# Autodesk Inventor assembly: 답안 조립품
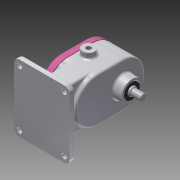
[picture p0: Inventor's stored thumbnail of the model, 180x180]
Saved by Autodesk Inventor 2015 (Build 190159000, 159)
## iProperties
Created: 2020-09
Part Number: 답안 조립품
Document SubType Name: Assembly
Designer: 1015698
Author: 1015698
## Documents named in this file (11)
- C:\Users\1015698\Desktop\700906V1049\답안 조립품.iam
- C:\Users\1015698\Desktop\700906V1049\20200919 부품.ipt
- C:\Users\1015698\Desktop\700906V1049\메인축.ipt
- C:\Users\1015698\Desktop\700906V1049\키 6 x 6 x 18.ipt
- C:\Users\1015698\Desktop\700906V1049\스퍼기어.ipt
- C:\Users\1015698\Desktop\700906V1049\베어링부시.ipt
- C:\Users\1015698\Desktop\700906V1049\서브축.ipt
- C:\Users\1015698\Desktop\700906V1049\개스킷.ipt
- C:\Users\1015698\Desktop\700906V1049\커버.ipt
- C:\Users\1015698\Desktop\700906V1049\오일 실 16 28 7.ipt
- C:\Users\1015698\Desktop\700906V1049\볼트 M5.ipt
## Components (2 placed, 2 different names)
1. 20200919 부품:1
2. 개스킷:1
